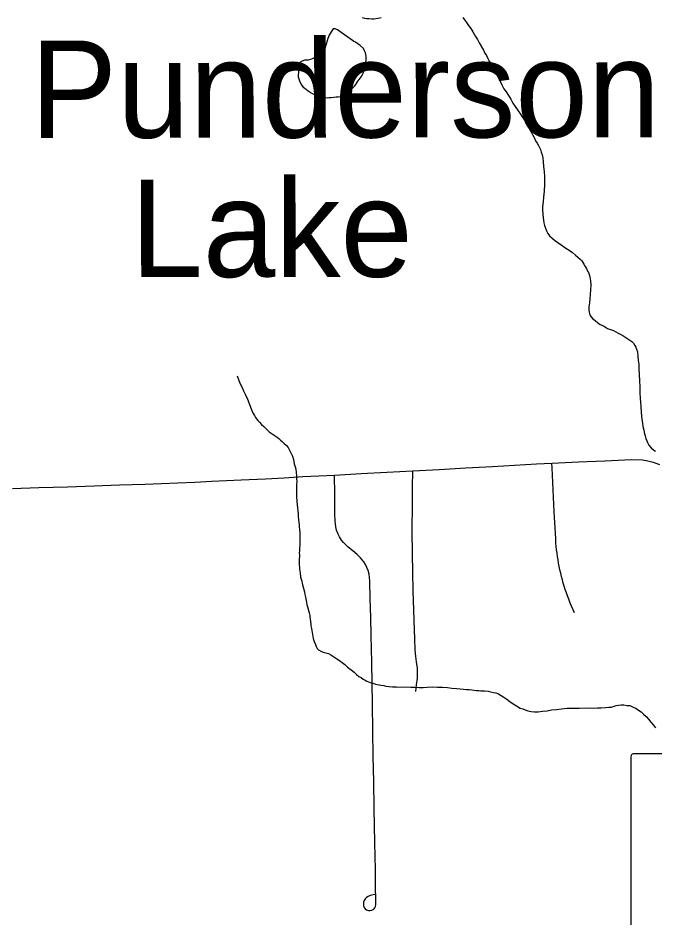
# Model space of a CAD drawing. Extents: x 103424 to 290657, y 38711 to 110967.
# Drawn here: x 140062 to 144013, y 49490 to 55076 of the extents above; entities that cross this region are included whole.
import ezdxf

# ---------------------------------------------------------------- set-up
doc = ezdxf.new("R2010")
doc.units = 0
for name, color, linetype in [('GM_X_Major_Lake_Text', 7, 'Continuous'), ('GM_X_Minor_Lake', 7, 'Continuous'), ('GM_X_Minor_River', 7, 'Continuous'), ('GM_X_State_Shield', 7, 'Continuous'), ('GM_X_Township_Road', 7, 'Continuous')]:
    doc.layers.add(name, color=color, linetype=linetype)

msp = doc.modelspace()

# ---------------------------------------------------------------- linework, layer by layer
at = {"layer": 'GM_X_Minor_Lake'}
for points in [[(142058.7, 54992.1), (142044.3, 55001.9), (142028.1, 55007.6), (142015.9, 55009.3), (142004.2, 54988.9), (141992.5, 54968.4), (141982.8, 54948.1), (141979.1, 54933.8), (141973.5, 54913.5), (141967.8, 54893.2), (141964, 54883), (141952.2, 54868.6), (141930.4, 54850), (141914.5, 54837.5), (141898.5, 54829.1), (141886.5, 54822.8), (141876.5, 54818.5), (141860.4, 54814.1), (141840.2, 54813.7), (141824.1, 54807.3), (141812.2, 54801), (141806.4, 54788.8), (141804.5, 54778.6), (141802.8, 54764.4), (141801.1, 54750.3), (141800, 54709.9), (141804.3, 54697.8), (141808.5, 54685.8), (141815, 54667.8), (141821.3, 54655.8), (141829.6, 54645.9), (141839.9, 54640.1), (141850.1, 54632.2), (141860.4, 54624.4), (141880.9, 54610.7), (141899.3, 54601), (141917.6, 54593.3), (141936, 54585.6), (141954.3, 54582), (141968.4, 54582.3), (141978.6, 54580.5), (141990.6, 54582.8), (142004.8, 54583.1), (142020.9, 54583.4), (142035, 54585.8), (142047.2, 54586), (142065.3, 54588.5), (142075.4, 54590.7), (142087.3, 54599), (142097.3, 54605.3), (142109.2, 54615.6), (142119.1, 54621.9), (142129, 54632.2), (142138.9, 54642.5), (142148.8, 54652.8), (142156.7, 54663.1), (142170.4, 54683.6), (142180.2, 54695.9), (142190, 54710.3), (142197.8, 54724.6), (142203.6, 54736.8), (142207.4, 54749), (142213.2, 54761.3), (142215, 54773.4), (142216.7, 54787.6), (142218.4, 54801.8), (142220.2, 54813.9), (142221.9, 54828.1), (142221.7, 54838.2), (142219.4, 54848.2), (142217.1, 54860.3), (142210.8, 54872.2), (142204.5, 54886.2), (142183.9, 54904), (142169.5, 54915.8), (142155.1, 54925.5), (142144.9, 54929.4), (142135.8, 54936.1)], [(142135.8, 54936.1), (142058.7, 54992.1)]]:
    msp.add_lwpolyline(points, dxfattribs=at)
at = {"layer": 'GM_X_Minor_River'}
for points in [[(142196.3, 55077.9), (142210.6, 55074.1), (142224.7, 55072.4), (142236.9, 55072.7), (142257.1, 55071.1), (142269.2, 55071.4), (142281.3, 55071.6), (142295.4, 55074), (142313.5, 55078.4)], [(142820.8, 55079.3), (142831.3, 55063.4), (142843.7, 55047.5), (142856.2, 55029.6), (142870.8, 55009.8), (142883.4, 54989.8), (142900.1, 54961.9), (142910.7, 54942), (142921.2, 54922), (142948.4, 54876.2), (142956.9, 54858.2), (142967.4, 54842.3), (142975.8, 54824.3), (142984.3, 54808.3), (142994.7, 54792.4), (143005.3, 54768.4), (143017.9, 54748.5), (143028.5, 54726.5), (143039, 54706.5), (143051.6, 54684.6), (143062.2, 54660.6), (143074.8, 54636.7), (143089.4, 54616.8), (143104, 54594.9), (143118.7, 54571), (143131.3, 54547), (143145.9, 54527.2), (143164.7, 54499.3), (143179.2, 54479.4), (143189.7, 54461.5), (143202.3, 54441.6), (143212.8, 54423.6), (143223.3, 54405.7), (143231.7, 54389.7), (143240.1, 54375.8), (143248.4, 54361.8), (143254.8, 54347.8), (143263.2, 54333.9), (143271.7, 54313.9), (143282.1, 54298), (143290.5, 54284), (143296.8, 54272), (143303.2, 54260.1), (143307.6, 54244), (143312, 54225.9), (143316.4, 54207.9), (143318.9, 54183.7), (143321.6, 54155.5), (143324.3, 54121.2), (143327, 54091), (143328, 54044.6), (143324.9, 54000.1), (143321.6, 53963.7), (143318.1, 53937.4), (143316.5, 53919.2), (143314.8, 53903)], [(143314.8, 53903), (143315.1, 53892.9), (143315.3, 53882.8), (143318.3, 53836.4), (143320.6, 53820.3), (143323, 53804.2), (143327.4, 53788.2), (143333.8, 53772.1), (143340.3, 53754.1), (143348.7, 53738.1), (143359.1, 53724.2), (143373.5, 53710.4), (143390, 53696.7), (143410.5, 53683), (143431, 53667.3), (143459.7, 53647.7), (143480.3, 53634), (143500.8, 53620.3), (143519.3, 53604.6), (143533.7, 53590.8), (143548.1, 53579), (143558.4, 53569.1), (143564.7, 53559.1), (143571, 53547.2), (143579.4, 53533.2), (143587.8, 53521.3), (143594.2, 53505.3), (143600.4, 53495.3), (143604.7, 53483.3), (143609.1, 53469.2), (143611.6, 53445.1), (143614.2, 53416.9), (143612.8, 53388.6), (143611.4, 53360.3), (143607.9, 53334), (143606.5, 53307.7), (143602.9, 53283.4), (143601.3, 53265.2), (143603.7, 53249.1), (143608.1, 53233), (143614.3, 53223.1), (143626.8, 53209.2), (143641.2, 53197.4), (143655.6, 53185.6), (143672, 53173.8), (143692.4, 53164.2), (143719, 53148.6), (143755.7, 53135.3), (143784.3, 53119.8), (143812.9, 53104.2), (143868.3, 53067.1), (143878.6, 53057.2), (143887, 53043.3), (143893.3, 53033.3), (143897.6, 53019.3), (143904, 53003.3), (143906.6, 52975), (143909.1, 52952.9), (143911.7, 52926.7), (143912.3, 52898.5), (143915.1, 52862.2), (143915.9, 52823.8), (143918.8, 52785.5), (143919.5, 52749.2), (143920.2, 52716.9), (143922.9, 52688.7), (143925.4, 52664.6), (143926.1, 52630.2), (143928.7, 52606.1), (143931.2, 52583.9), (143935.7, 52561.8), (143938.2, 52539.7), (143942.7, 52517.6), (143947.2, 52495.4), (143951.5, 52481.4), (143955.9, 52465.3), (143962.3, 52451.4), (143966.5, 52441.4), (143975, 52425.4), (143989.5, 52407.5), (144006, 52393.8), (144016.2, 52387.9)], [(141421.2, 52854.3), (141423.4, 52848.3), (141429.8, 52832.3), (141438.3, 52810.3), (141448.9, 52786.3), (141459.6, 52762.3), (141472.2, 52736.3), (141484.9, 52710.4), (141495.6, 52682.3), (141504.2, 52660.3), (141512.7, 52640.3), (141519.2, 52620.3), (141527.5, 52608.3), (141533.9, 52596.4), (141548.4, 52578.5), (141558.7, 52566.6), (141571.2, 52552.7), (141585.6, 52541), (141600.1, 52525.1), (141618.6, 52507.4), (141637.1, 52495.6), (141651.4, 52485.9), (141669.9, 52474.1), (141680.1, 52466.3), (141690.4, 52456.4), (141700.8, 52446.6), (141713.1, 52434.7), (141727.5, 52422.9), (141738, 52409), (141746.4, 52393), (141754.8, 52377.1), (141763.3, 52357.1), (141769.8, 52335), (141774.4, 52308.9), (141780.9, 52290.8), (141785.3, 52274.8), (141787.7, 52254.6), (141788.2, 52234.5), (141788.6, 52216.3), (141791, 52198.2), (141789.4, 52178), (141789.9, 52151.7), (141788.4, 52127.5), (141789, 52103.3), (141792.1, 52052.8), (141794.4, 52036.8), (141796.9, 52016.6), (141799.3, 51998.5), (141799.7, 51980.3), (141802.1, 51962.2), (141802.5, 51944.1), (141804.8, 51930), (141805, 51917.9), (141807.4, 51901.8), (141809.9, 51877.6), (141810.5, 51853.4), (141809, 51829.1), (141809.4, 51806.9), (141807.9, 51784.7), (141808.2, 51768.5), (141806.5, 51756.4), (141806.7, 51744.3), (141807, 51734.2), (141805.3, 51718), (141805.5, 51705.9), (141805.8, 51691.8), (141806.1, 51681.7), (141808.4, 51665.6), (141808.6, 51655.5), (141811.2, 51629.3), (141813.7, 51607.2), (141818.1, 51593.1), (141822.4, 51581.1), (141824.7, 51567), (141826.9, 51557), (141831.3, 51542.9), (141833.6, 51528.9), (141837.9, 51514.8), (141840.3, 51496.7), (141844.7, 51480.7), (141849.2, 51460.6), (141853.7, 51436.4), (141860.5, 51406.3), (141867, 51384.2), (141871.4, 51368.2), (141871.6, 51358.1), (141873.9, 51344), (141878.6, 51313.8), (141878.8, 51303.7), (141881.2, 51287.6), (141883.5, 51273.6), (141888.1, 51249.4), (141892.6, 51225.3), (141899.1, 51205.3), (141907.6, 51187.3), (141911.9, 51175.3), (141918.2, 51163.3), (141924.5, 51153.3), (141940.8, 51145.6), (141955.1, 51139.9), (141971.3, 51136.2)], [(141971.3, 51136.2), (141987.6, 51130.5), (142001.9, 51122.7), (142020.4, 51111), (142038.8, 51099.3), (142055.2, 51087.5), (142071.7, 51075.8), (142088.1, 51064), (142104.6, 51046.2), (142127.2, 51030.6), (142145.7, 51014.8), (142160.2, 51001), (142176.6, 50989.2), (142190.9, 50981.5), (142203.2, 50971.6), (142215.5, 50965.9), (142225.7, 50960), (142235.9, 50956.2), (142246.1, 50952.4), (142256.3, 50948.6), (142268.5, 50944.8), (142278.7, 50941), (142288.8, 50939.2), (142303, 50937.5), (142313.1, 50935.7), (142331.4, 50932), (142343.6, 50928.3), (142361.8, 50926.6), (142384.1, 50925.1), (142408.4, 50923.6), (142497.4, 50921.5), (142523.6, 50922.1), (142549.9, 50920.7), (142574.2, 50921.2), (142600.4, 50921.7), (142630.7, 50924.4), (142663.1, 50923.1), (142695.4, 50921.8), (142725.8, 50920.4), (142752.1, 50917), (142782.5, 50913.6), (142804.8, 50912.1), (142825, 50910.5), (142843.3, 50908.9), (142859.5, 50907.2), (142875.7, 50905.5), (142889.8, 50903.8), (142904, 50902.1), (142920.2, 50902.5), (142932.4, 50900.7), (142942.5, 50898.9), (142954.6, 50899.2), (142976.9, 50897.6), (142993.1, 50893.9), (143011.4, 50890.3), (143025.6, 50886.6), (143041.9, 50880.9), (143058.3, 50871.1), (143074.7, 50861.4), (143093.2, 50847.7), (143111.6, 50833.9), (143132.2, 50818.2), (143152.7, 50806.6), (143177.2, 50793), (143193.5, 50787.3), (143207.8, 50781.5), (143224, 50775.8), (143244.3, 50772.2), (143264.6, 50768.6), (143288.9, 50769.2), (143315, 50773.8), (143343.3, 50776.4), (143371.5, 50781.1), (143401.7, 50783.7), (143432, 50788.4), (143468.3, 50791.2), (143488.5, 50791.7), (143506.7, 50792.1), (143524.8, 50792.5), (143543, 50792.9), (143611.7, 50794.3), (143634, 50792.8), (143656.2, 50793.3), (143678.4, 50793.8), (143706.6, 50796.4), (143726.8, 50798.9), (143741, 50799.2), (143759.1, 50803.6), (143771.1, 50807.9), (143787.2, 50810.3), (143803.3, 50812.7), (143819.5, 50813), (143837.8, 50809.4), (143856, 50807.8), (143872.3, 50800), (143896.8, 50790.5), (143911.2, 50778.7), (143927.5, 50768.9), (143942, 50755.1), (143958.4, 50741.3), (143973, 50723.5)], [(143973, 50723.5), (143987.5, 50705.6), (144002, 50687.8), (144016.6, 50669.9)]]:
    msp.add_lwpolyline(points, dxfattribs=at)
at = {"layer": 'GM_X_State_Shield'}
for p, q in [((144287.5, 50509.2), (143877.2, 50509.2)), ((143863.5, 50490.9), (143863.5, 49427.7))]:
    msp.add_line(p, q, dxfattribs=at)
msp.add_arc((143879.5, 50493.2), 16.2, 98.1301, 188.1301, dxfattribs=at)
at = {"layer": 'GM_X_Township_Road'}
for points in [[(140026.6, 52156.5), (140191.6, 52161.1), (140280.1, 52163.6), (140368.6, 52166.2), (140533.5, 52171.9), (140691, 52177.5), (140848.5, 52183), (140950.8, 52187), (141053, 52191.1), (141157.8, 52195.8), (141262.6, 52200.6), (141354.5, 52205), (141446.5, 52209.4), (141596, 52216), (141712.5, 52222.6), (141829, 52229.2), (141926.8, 52234), (142024.5, 52238.7), (142189.3, 52247.6), (142349.5, 52256.2), (142509.7, 52264.8), (142674.5, 52274.2), (142839.3, 52283.6), (143004.1, 52293), (143141, 52300.7), (143278, 52308.5), (143372.6, 52313.5), (143537.5, 52320.7), (143702.4, 52327.8), (143784.9, 52331.4), (143867.4, 52335.1), (143935.8, 52332.9), (143968.7, 52327), (144000.9, 52319.3), (144040, 52305.1)], [(143512.6, 51383.8), (143487.3, 51443.8), (143477.7, 51468.9), (143470.4, 51488.7), (143463.1, 51508.5), (143456.3, 51528.4), (143450, 51548.5), (143443.7, 51568.7), (143438, 51589), (143432.7, 51609.4), (143427.7, 51629.9), (143422.9, 51650.4), (143418.6, 51671), (143414.6, 51691.8), (143411.1, 51712.6), (143407.8, 51733.4), (143405.1, 51754.3), (143402.6, 51775.2), (143400.3, 51796.2), (143398.5, 51817.2), (143396.8, 51845.3), (143388.2, 52010.1), (143381.2, 52146.7), (143374.1, 52283.3), (143372.6, 52313.5)], [(142275.3, 49636.4), (142245.6, 49628.6), (142232.9, 49623.7), (142223.1, 49617.1), (142215.2, 49609.3), (142208.9, 49599.3), (142205.2, 49587.8), (142203.7, 49576.3), (142205, 49565), (142208.9, 49555.5), (142215.6, 49546.3), (142223.8, 49540.3), (142234.9, 49537), (142246.7, 49536.3), (142257.1, 49538.5), (142267.9, 49544.4), (142274.2, 49552.9), (142278.3, 49561.9), (142280.1, 49572.6), (142281.2, 49586), (142279.5, 49701.8), (142278.6, 49790.7), (142275.5, 49955.7), (142273.4, 50063), (142271.4, 50170.2), (142268.2, 50335.2), (142265.2, 50493.7), (142262.1, 50652.2), (142259.9, 50817.3), (142258.1, 50947.7), (142256.3, 51078.1), (142252.4, 51243.2), (142249.7, 51357.1), (142246.9, 51471.1), (142244.3, 51582.1), (142242.4, 51603), (142238.9, 51624.7), (142233, 51646.5), (142225.6, 51665.3), (142216.1, 51684.6), (142205.8, 51700.9), (142186.4, 51724.3), (142165.3, 51746.1), (142137.6, 51769.1), (142110.3, 51791.4), (142093, 51807.2), (142081.2, 51820.1), (142069, 51834), (142055.9, 51854.7), (142047.1, 51873), (142038.1, 51896.7), (142033.3, 51918.6), (142030.3, 51935.8), (142028.3, 51953.3), (142027.6, 51997.4), (142025.8, 52118.1), (142024.5, 52238.7)], [(142528.9, 50895.5), (142534.2, 50936.9), (142539.3, 50977.6), (142540.3, 51006.7), (142538.8, 51040.8), (142533.2, 51080.1), (142528.6, 51112.1), (142524.6, 51151.5), (142523.5, 51222.2), (142521.9, 51277.9), (142517.8, 51399.4), (142513.6, 51520.8), (142511.3, 51635.4), (142509, 51750), (142507.3, 51892.9), (142508.3, 52057.9), (142509, 52161.4), (142509.7, 52264.8)]]:
    msp.add_lwpolyline(points, dxfattribs=at)

# ---------------------------------------------------------------- texts
at = {"layer": 'GM_X_Major_Lake_Text'}
for s, height, rotation, p in [('Punderson', 604.13, 0.0666, (140137.6, 54331.5)), ('Lake', 604.12, 0.0665, (140759.3, 53467.7))]:
    msp.add_text(s, height=height, rotation=rotation, dxfattribs=at).set_placement(p)

doc.saveas('drawing.dxf')
